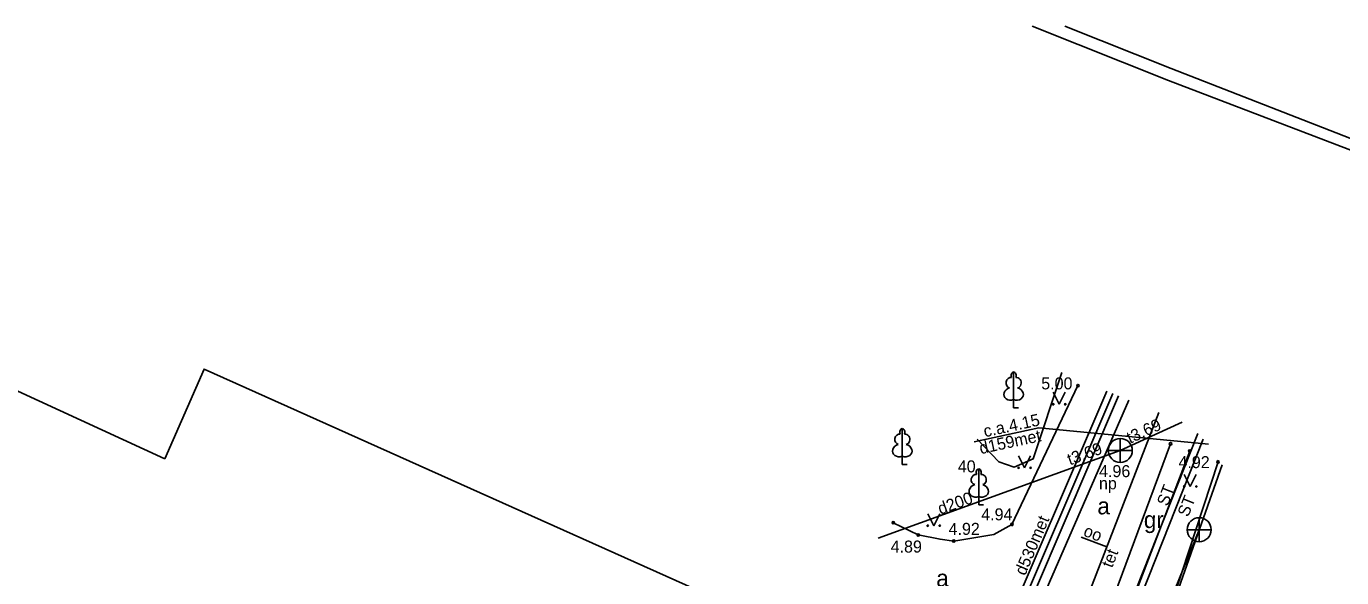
# Model space of a CAD drawing. Extents: x 484635 to 484808, y 278866 to 278977.
# Drawn here: x 484724.7 to 484779.6, y 278953.8 to 278976.7 of the extents above; entities that cross this region are included whole.
import ezdxf

# ---------------------------------------------------------------- set-up
doc = ezdxf.new("R2010")
doc.units = 0
for name, color, linetype in [('APGS_VADP_ZSPR_####_#', 7, 'Continuous'), ('BUVE_EKAS_####_####_#', 7, 'Continuous'), ('CELI_CAPM_####_####_#', 7, 'Continuous'), ('CELI_CMAL_####_####_#', 7, 'Continuous'), ('CELI_CSEG_####_TKST_#', 7, 'Continuous'), ('ELEK_VADP_ZSPR_####_#', 7, 'Continuous'), ('ELEK_VADP_ZSPR_TKST_#', 7, 'Continuous'), ('GAZE_VADP_KONT_####_#', 7, 'Continuous'), ('GAZE_VADP_VSP2_####_#', 7, 'Continuous'), ('GAZE_VADP_VSP2_TKST_#', 7, 'Continuous'), ('GAZE_VADP_ZSPD_####_#', 7, 'Continuous'), ('GAZE_VADP_ZSPD_TKST_#', 7, 'Continuous'), ('NORB_ZOGS_ZSTP_####_#', 7, 'Continuous'), ('RELJ_AATZ_####_TKST_#', 7, 'Continuous'), ('RELJ_ELEM_####_####_#', 7, 'Continuous'), ('SAKK_IZVK_####_TKST_#', 7, 'Continuous'), ('SAKK_KKAN_####_####_#', 7, 'Continuous'), ('SAKK_KKAN_####_TKST_#', 7, 'Continuous'), ('SILT_VADP_UDEN_####_#', 7, 'Continuous'), ('SKAN_ELEM_####_####_#', 7, 'Continuous'), ('SKAN_ELEM_PAST_TKST_#', 7, 'Continuous'), ('SKAN_VADP_NEDR_####_#', 7, 'Continuous'), ('SKAN_VADP_PAST_####_#', 7, 'Continuous'), ('SKAN_VADP_PAST_TKST_#', 7, 'Continuous'), ('TERT_DIAM_####_TKST_#', 7, 'Continuous'), ('TERT_ELEM_####_####_#', 7, 'Continuous'), ('TERT_KRND_####_####_#', 7, 'Continuous')]:
    doc.layers.add(name, color=color, linetype=linetype)

msp = doc.modelspace()

# ---------------------------------------------------------------- linework, layer by layer
at = {"layer": 'APGS_VADP_ZSPR_####_#'}
for points in [[(484764.353, 278959.528), (484765.258, 278958.581), (484765.892, 278958.361), (484766.689, 278958.706), (484767.889, 278962.303)], [(484758.95, 278942.999), (484764.131, 278940.921), (484767.852, 278949.207), (484766.539, 278950.935), (484767.13, 278953.024), (484770.675, 278961.156)]]:
    msp.add_lwpolyline(points, dxfattribs=at)
at = {"layer": 'BUVE_EKAS_####_####_#'}
msp.add_line((484701.308, 278972.123), (484730.484, 278958.706), dxfattribs=at)
msp.add_lwpolyline([(484758.206, 278950.764), (484732.124, 278962.447), (484730.484, 278958.706)], dxfattribs=at)
at = {"layer": 'CELI_CAPM_####_####_#'}
for points in [[(484760.858, 278956.044), (484761.9, 278955.538), (484762.805, 278955.359), (484763.38, 278955.28), (484765.048, 278955.557), (484765.803, 278955.972), (484768.557, 278961.757)], [(484772.416, 278959.332), (484769.549, 278951.63), (484765.628, 278941.251)]]:
    msp.add_lwpolyline(points, dxfattribs=at)
at = {"layer": 'CELI_CMAL_####_####_#'}
msp.add_lwpolyline([(484769.329, 278939.508), (484768.78, 278938.437), (484767.726, 278939.35), (484767.002, 278941.284), (484768.207, 278945.747), (484770.564, 278952.099), (484773.219, 278959.033)], dxfattribs=at)
at = {"layer": 'ELEK_VADP_ZSPR_####_#'}
for points in [[(484761.125, 278947.29), (484769.574, 278949.742), (484773.55, 278959.756)], [(484773.782, 278959.529), (484769.799, 278949.495), (484762.476, 278947.375), (484761.122, 278944.061), (484760.097, 278944.48), (484759.99, 278944.218), (484761.033, 278943.792), (484759.305, 278940.39), (484755.946, 278931.315), (484750.993, 278921.676), (484747.073, 278922.96), (484745.044, 278923.863)]]:
    msp.add_lwpolyline(points, dxfattribs=at)
at = {"layer": 'GAZE_VADP_KONT_####_#'}
for points in [[(484750.477, 278882.479), (484757.277, 278895.824), (484768.894, 278918.779), (484766.279, 278933.523), (484765.094, 278950.654), (484769.76, 278961.533)], [(484751.36, 278883.044), (484757.749, 278895.584), (484769.446, 278918.697), (484766.805, 278933.587), (484765.632, 278950.562), (484770.25, 278961.331)]]:
    msp.add_lwpolyline(points, dxfattribs=at)
at = {"layer": 'GAZE_VADP_VSP2_####_#'}
msp.add_lwpolyline([(484750.918, 278882.762), (484757.513, 278895.704), (484769.17, 278918.738), (484766.542, 278933.555), (484765.363, 278950.608), (484770.005, 278961.432)], dxfattribs=at)
at = {"layer": 'GAZE_VADP_ZSPD_####_#'}
msp.add_lwpolyline([(484764.233, 278959.413), (484766.93, 278959.993), (484774.004, 278959.313)], dxfattribs=at)
at = {"layer": 'NORB_ZOGS_ZSTP_####_#'}
msp.add_lwpolyline([(484774.397, 278958.581), (484772.581, 278953.036)], dxfattribs=at)
at = {"layer": 'RELJ_ELEM_####_####_#'}
for centre in [(484768.557, 278961.757), (484772.416, 278959.332), (484773.219, 278959.033), (484774.397, 278958.581), (484760.858, 278956.044), (484765.803, 278955.972), (484761.9, 278955.538), (484763.38, 278955.28)]:
    msp.add_circle(centre, 0.05, dxfattribs=at)
at = {"layer": 'SAKK_IZVK_####_TKST_#'}
msp.add_line((484769.758, 278955.035), (484768.689, 278955.449), dxfattribs=at)
at = {"layer": 'SAKK_KKAN_####_####_#'}
msp.add_lwpolyline([(484768.008, 278950.519), (484771.93, 278960.64)], dxfattribs=at)
at = {"layer": 'SILT_VADP_UDEN_####_#'}
for points in [[(484807.573, 278960.751), (484806.818, 278961.065), (484798.835, 278964.17), (484780.584, 278971.316), (484772.333, 278974.469), (484766.644, 278976.726)], [(484768.01, 278976.726), (484772.449, 278974.964), (484780.717, 278971.748), (484799.046, 278964.702), (484806.928, 278961.529), (484807.573, 278961.261)]]:
    msp.add_lwpolyline(points, dxfattribs=at)
at = {"layer": 'SKAN_ELEM_####_####_#'}
for p, q in [((484770.322, 278958.557), (484770.322, 278959.557)), ((484769.822, 278959.057), (484770.822, 278959.057)), ((484773.613, 278955.255), (484773.613, 278956.255)), ((484774.113, 278955.755), (484773.113, 278955.755))]:
    msp.add_line(p, q, dxfattribs=at)
for centre in [(484770.322, 278959.057), (484773.613, 278955.755)]:
    msp.add_circle(centre, 0.5, dxfattribs=at)
at = {"layer": 'SKAN_VADP_NEDR_####_#'}
msp.add_lwpolyline([(484762.372, 278929.106), (484768.919, 278944.203), (484773.613, 278955.755)], dxfattribs=at)
at = {"layer": 'SKAN_VADP_PAST_####_#'}
msp.add_lwpolyline([(484760.223, 278955.397), (484770.322, 278959.057), (484772.899, 278960.241)], dxfattribs=at)
at = {"layer": 'TERT_ELEM_####_####_#'}
for p, q in [((484767.527, 278961.481), (484767.777, 278960.981)), ((484767.777, 278960.981), (484768.027, 278961.481)), ((484765.875, 278961.173), (484765.875, 278960.826)), ((484765.875, 278960.826), (484766.075, 278960.826)), ((484761.233, 278958.815), (484761.233, 278958.468)), ((484766.081, 278958.834), (484766.331, 278958.334)), ((484766.331, 278958.334), (484766.581, 278958.834)), ((484761.233, 278958.468), (484761.433, 278958.468)), ((484772.991, 278958.057), (484773.241, 278957.557)), ((484773.241, 278957.557), (484773.491, 278958.057)), ((484764.421, 278957.135), (484764.421, 278956.788)), ((484764.421, 278956.788), (484764.621, 278956.788)), ((484762.293, 278956.422), (484762.543, 278955.922)), ((484762.543, 278955.922), (484762.793, 278956.422))]:
    msp.add_line(p, q, dxfattribs=at)
for points in [[(484765.875, 278962.326), (484765.875, 278961.173)], [(484765.964, 278962.094), (484765.963, 278962.095)], [(484761.233, 278959.968), (484761.233, 278958.815)], [(484761.322, 278959.735), (484761.321, 278959.736)], [(484764.421, 278958.288), (484764.421, 278957.135)], [(484764.51, 278958.056), (484764.509, 278958.056)]]:
    msp.add_lwpolyline(points, dxfattribs=at)
for centre, radius in [((484767.526, 278960.981), 0.028), ((484768.026, 278960.981), 0.0263), ((484766.081, 278958.333), 0.028), ((484766.581, 278958.333), 0.0263), ((484772.99, 278957.556), 0.028), ((484773.49, 278957.556), 0.0263), ((484762.293, 278955.922), 0.028), ((484762.793, 278955.922), 0.0263)]:
    msp.add_circle(centre, radius, dxfattribs=at)
for centre, major_axis, ratio, start_param, end_param in [((484765.746, 278961.881), (-0.039, -0.212), 0.861323, 3.141593, 6.283185), ((484765.875, 278962.176), (0, -0.15), 0.707107, 3.14537, 5.287485), ((484765.874, 278962.176), (0, -0.15), 0.707107, 0.995701, 3.137816), ((484766.003, 278961.881), (0.039, -0.212), 0.861323, 0, 3.141593), ((484765.785, 278961.419), (0.307, 0.095), 0.814445, 1.570796, 4.752015), ((484765.964, 278961.419), (-0.307, 0.095), 0.814445, 1.531171, 4.712389), ((484761.233, 278959.818), (0, -0.15), 0.707107, 3.14537, 5.287485), ((484761.232, 278959.818), (0, -0.15), 0.707107, 0.995701, 3.137816), ((484761.143, 278959.061), (0.307, 0.095), 0.814445, 1.570796, 4.752015), ((484761.105, 278959.523), (-0.039, -0.212), 0.861323, 3.141593, 6.283185), ((484761.322, 278959.061), (-0.307, 0.095), 0.814445, 1.531171, 4.712389), ((484761.361, 278959.523), (0.039, -0.212), 0.861323, 0, 3.141593), ((484764.421, 278958.138), (0, -0.15), 0.707107, 3.14537, 5.287485), ((484764.42, 278958.138), (0, -0.15), 0.707107, 0.995701, 3.137816), ((484764.331, 278957.381), (0.307, 0.095), 0.814445, 1.570796, 4.752015), ((484764.293, 278957.843), (-0.039, -0.212), 0.861323, 3.141593, 6.283185), ((484764.51, 278957.381), (-0.307, 0.095), 0.814445, 1.531171, 4.712389), ((484764.549, 278957.843), (0.039, -0.212), 0.861323, 0, 3.141593)]:
    msp.add_ellipse(centre, major_axis=major_axis, ratio=ratio, start_param=start_param, end_param=end_param, dxfattribs=at)
at = {"layer": 'TERT_KRND_####_####_#'}
msp.add_lwpolyline([(484772.663, 278953.05), (484774.563, 278958.46)], dxfattribs=at)

# ---------------------------------------------------------------- texts
at = {"layer": 'CELI_CSEG_####_TKST_#'}
for s, p in [('a', (484769.367, 278956.395)), ('gr', (484771.304, 278955.82)), ('a', (484762.648, 278953.385))]:
    msp.add_text(s, height=0.7, dxfattribs=at).set_placement(p)
at = {"layer": 'ELEK_VADP_ZSPR_TKST_#'}
for rotation, p in [(68.798, (484772.294, 278956.702)), (68.3466, (484773.153, 278956.255))]:
    msp.add_text('ST', height=0.5, rotation=rotation, dxfattribs=at).set_placement(p)
at = {"layer": 'GAZE_VADP_VSP2_TKST_#'}
msp.add_text('d530met', height=0.5, rotation=66.7876, dxfattribs=at).set_placement((484766.351, 278953.812))
at = {"layer": 'GAZE_VADP_ZSPD_TKST_#'}
for s, p in [('c.a.4.15', (484764.676, 278959.605)), ('d159met', (484764.503, 278958.9))]:
    msp.add_text(s, height=0.5, rotation=12.1458, dxfattribs=at).set_placement(p)
at = {"layer": 'RELJ_AATZ_####_TKST_#'}
for s, p in [('5.00', (484767.026, 278961.601)), ('4.92', (484772.747, 278958.319)), ('4.94', (484764.524, 278956.144)), ('4.92', (484763.163, 278955.539)), ('4.89', (484760.748, 278954.803))]:
    msp.add_text(s, height=0.5, dxfattribs=at).set_placement(p)
at = {"layer": 'SAKK_IZVK_####_TKST_#'}
msp.add_text('oo', height=0.5, rotation=158.8189, dxfattribs=at).set_placement((484769.581, 278955.604))
at = {"layer": 'SAKK_KKAN_####_TKST_#'}
msp.add_text('tet', height=0.5, rotation=68.8189, dxfattribs=at).set_placement((484769.981, 278954.136))
at = {"layer": 'SKAN_ELEM_PAST_TKST_#'}
for s, p in [('4.96', (484769.437, 278957.945)), ('np', (484769.433, 278957.436))]:
    msp.add_text(s, height=0.5, dxfattribs=at).set_placement(p)
at = {"layer": 'SKAN_VADP_PAST_TKST_#'}
for s, rotation, p in [('t3.69', 24.6752, (484770.728, 278959.329)), ('t3.69', 19.9239, (484768.219, 278958.431)), ('d200', 19.9239, (484762.821, 278956.374))]:
    msp.add_text(s, height=0.5, rotation=rotation, dxfattribs=at).set_placement(p)
at = {"layer": 'TERT_DIAM_####_TKST_#'}
msp.add_text('40', height=0.5, dxfattribs=at).set_placement((484763.547, 278958.143))

doc.saveas('drawing.dxf')
